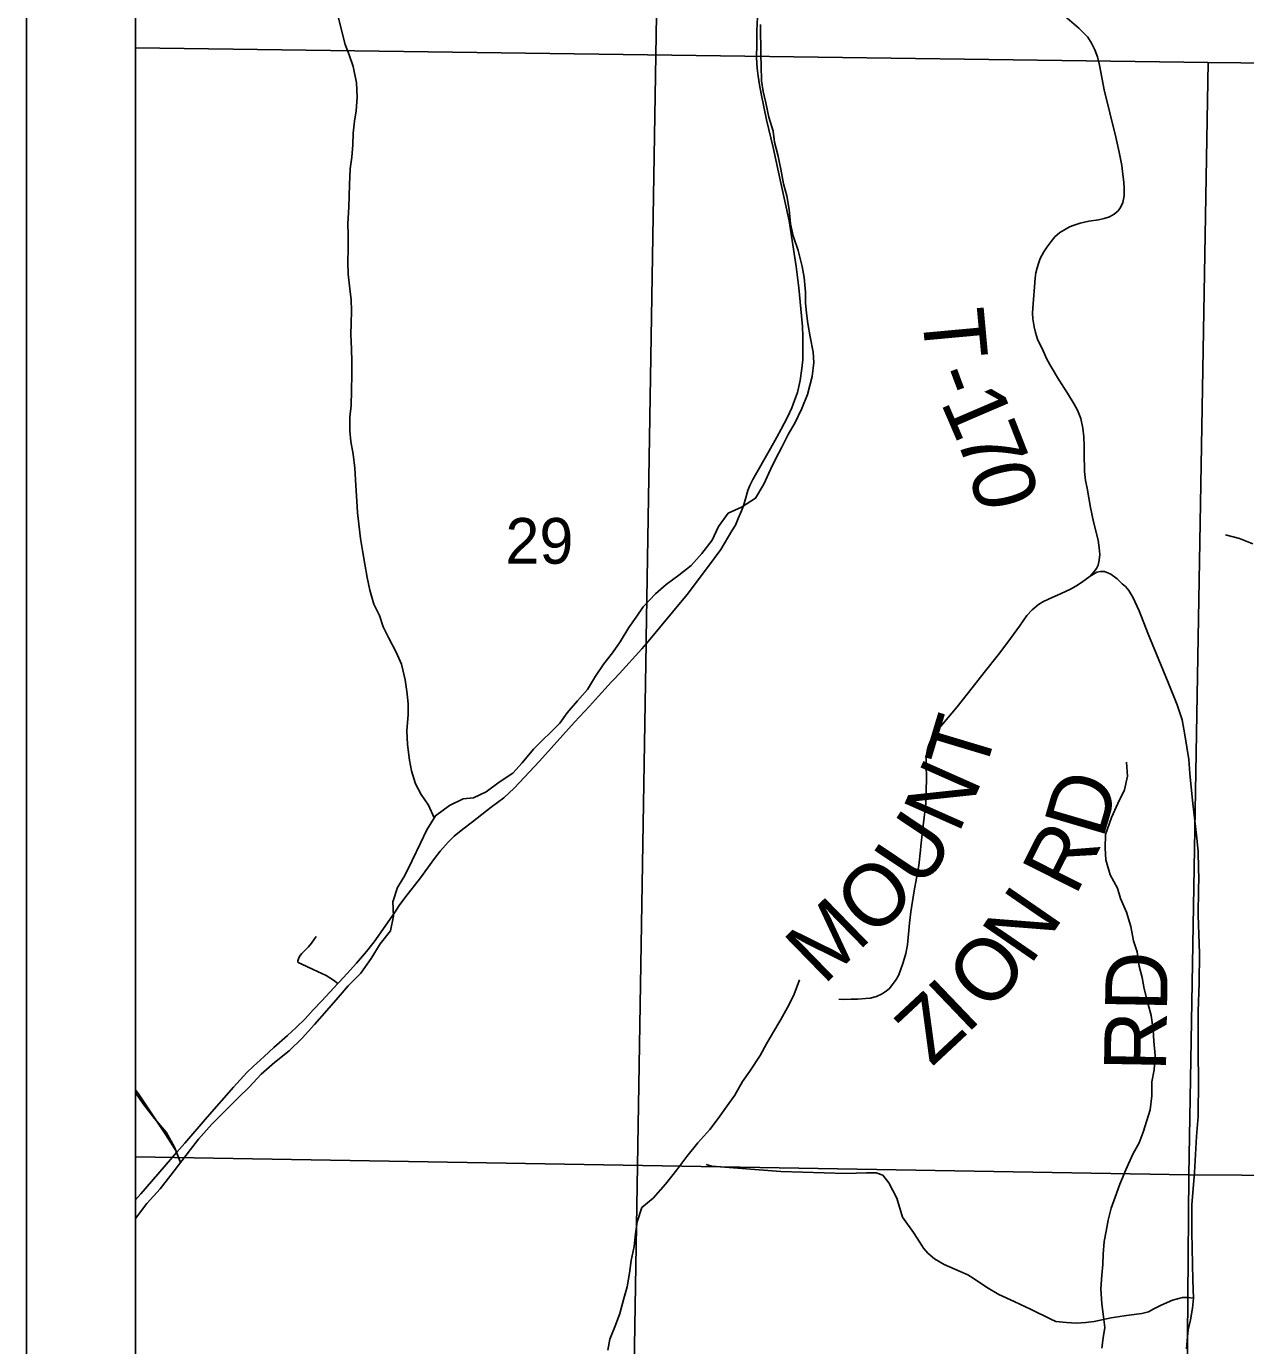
# Model space of a CAD drawing. Extents: x 0 to 34, y -8.9 to 22.
# Drawn here: x 23.617 to 24.734, y 10.111 to 11.32 of the extents above; entities that cross this region are included whole.
import ezdxf

# ---------------------------------------------------------------- set-up
doc = ezdxf.new("R2010")
doc.units = 0
for name, color, linetype in [('GM_X_Corporation', 7, 'Continuous'), ('GM_X_County_Road', 7, 'Continuous'), ('GM_X_Minor_River', 7, 'Continuous'), ('GM_X_Section_Text', 7, 'Continuous'), ('GM_X_Township_Road', 7, 'Continuous'), ('GM_X_Township_Road_Text', 7, 'Continuous'), ('SH_Data', 7, 'Continuous')]:
    doc.layers.add(name, color=color, linetype=linetype)

msp = doc.modelspace()

# ---------------------------------------------------------------- linework, layer by layer
at = {"layer": 'GM_X_Corporation'}
for points in [[(27.1396, 11.9157), (26.2139, 11.9314), (25.7578, 11.9372), (25.7218, 11.9377), (25.1035, 11.9505), (25.0773, 11.948), (24.3163, 11.9608), (24.2054, 11.9625), (24.1849, 11.9621), (23.7167, 11.9654), (23.7167, 7.104)], [(27.1396, 11.9157), (26.2139, 11.9314), (25.7578, 11.9372), (25.7218, 11.9377), (25.1035, 11.9505), (25.0773, 11.948), (24.3163, 11.9608), (24.2054, 11.9625), (24.2028, 11.8378), (24.2025, 11.824), (24.2007, 11.7362), (24.1845, 10.7587), (24.1844, 10.755), (24.1596, 9.2636)]]:
    msp.add_lwpolyline(points, dxfattribs=at)
for points in [[(23.7167, 11.9654), (23.7167, 9.2682), (24.0743, 9.2644), (24.1596, 9.2636), (24.1844, 10.755), (24.1845, 10.7587), (24.2007, 11.7362), (24.2025, 11.824), (24.2028, 11.8378), (24.2054, 11.9625), (24.1849, 11.9621)], [(23.7167, 11.3004), (23.7167, 10.2843), (24.6816, 10.2678), (24.6992, 11.287)], [(24.6992, 11.287), (25.7123, 11.2765), (25.698, 10.2614), (24.6816, 10.2678)], [(23.7167, 10.2843), (23.7167, 9.2652), (24.6733, 9.2562), (24.6816, 10.2678)], [(24.6816, 10.2678), (25.698, 10.2614), (25.683, 9.2467), (24.6733, 9.2562)]]:
    msp.add_lwpolyline(points, close=True, dxfattribs=at)
at = {"layer": 'GM_X_County_Road'}
for points in [[(24.1599, 10.7272), (24.1804, 10.7498), (24.1846, 10.7545), (24.2086, 10.7832), (24.2221, 10.7996), (24.2407, 10.8243), (24.2527, 10.8408), (24.263, 10.8578), (24.2662, 10.8631), (24.2688, 10.8692), (24.2718, 10.876), (24.2736, 10.8808), (24.2755, 10.8871), (24.2775, 10.8947), (24.2795, 10.8994), (24.2822, 10.9049), (24.2983, 10.9333), (24.3042, 10.9437), (24.3082, 10.9511), (24.3135, 10.9614), (24.3178, 10.9704), (24.3204, 10.9771), (24.323, 10.9847), (24.3254, 10.9954), (24.3271, 11.0065), (24.3279, 11.0145), (24.3279, 11.0221), (24.3279, 11.036), (24.3276, 11.0449), (24.3262, 11.0611), (24.3242, 11.0805), (24.3219, 11.1), (24.3195, 11.1159), (24.3153, 11.1417), (24.3082, 11.175), (24.3008, 11.2089), (24.2948, 11.2344), (24.2898, 11.2583), (24.2882, 11.2665), (24.287, 11.2743), (24.2862, 11.2817), (24.2854, 11.2911), (24.2857, 11.3038), (24.2859, 11.3163), (24.2863, 11.3286)], [(23.7167, 10.2448), (23.7216, 10.2503), (23.7545, 10.2886), (23.7617, 10.2966), (23.7824, 10.3205), (23.8065, 10.3482), (23.8187, 10.3614), (23.8243, 10.367), (23.8345, 10.3762), (23.8435, 10.3844), (23.856, 10.3955), (23.8637, 10.4026), (23.8719, 10.4108), (23.8794, 10.4188), (23.8873, 10.4272), (23.9019, 10.4429), (23.9033, 10.4444), (23.9104, 10.4522), (23.9191, 10.4617), (23.9283, 10.4723), (23.9354, 10.4811), (23.9538, 10.5078), (23.9583, 10.5144), (23.9634, 10.5215), (23.9778, 10.5399), (23.9905, 10.5576), (23.9957, 10.5644), (24.003, 10.5725), (24.0085, 10.5779), (24.0166, 10.5845), (24.0253, 10.5913), (24.0424, 10.6045), (24.0539, 10.6133), (24.0634, 10.622), (24.0868, 10.6468), (24.1189, 10.6825), (24.1324, 10.697), (24.1407, 10.7062), (24.1528, 10.7193), (24.1551, 10.7219), (24.1599, 10.7272)]]:
    msp.add_lwpolyline(points, dxfattribs=at)
at = {"layer": 'GM_X_Minor_River'}
for points in [[(23.9902, 10.5949), (23.9849, 10.6063), (23.9784, 10.6161), (23.973, 10.626), (23.9696, 10.6378), (23.9677, 10.6476), (23.9657, 10.6621), (23.9653, 10.6746), (23.9664, 10.6894), (23.9664, 10.6989), (23.9656, 10.7084), (23.9637, 10.7213), (23.9602, 10.7357), (23.9553, 10.7467), (23.9484, 10.76), (23.9435, 10.7699), (23.94, 10.7801), (23.9351, 10.7907), (23.9312, 10.8033), (23.9289, 10.815), (23.9266, 10.8272), (23.9247, 10.8397), (23.9228, 10.8507), (23.9212, 10.864), (23.9201, 10.8746), (23.9193, 10.8849), (23.9185, 10.8993), (23.9177, 10.9153), (23.9161, 10.9282), (23.9138, 10.9396), (23.913, 10.9494), (23.913, 10.962), (23.9141, 10.9726), (23.9145, 10.9863), (23.9148, 11.0011), (23.9148, 11.0129), (23.9144, 11.0243), (23.9139, 11.038), (23.9143, 11.0475), (23.9146, 11.0596), (23.9142, 11.0695), (23.9131, 11.0794), (23.9115, 11.093), (23.9111, 11.1037), (23.9115, 11.1166), (23.9114, 11.1291), (23.911, 11.139), (23.9121, 11.1546), (23.9125, 11.1645), (23.9128, 11.1751), (23.9132, 11.1895), (23.9147, 11.2002), (23.9158, 11.2116), (23.9161, 11.2222), (23.9172, 11.2332), (23.9187, 11.2427), (23.9198, 11.2553), (23.9191, 11.2682), (23.916, 11.2834), (23.9125, 11.294), (23.9087, 11.3035), (23.9053, 11.3164), (23.9026, 11.3278)], [(24.2143, 10.8171), (24.2256, 10.8259), (24.2355, 10.8369), (24.2449, 10.8491), (24.2506, 10.8617), (24.2597, 10.8739), (24.2718, 10.8796), (24.2847, 10.8876), (24.2922, 10.9006), (24.2983, 10.9139), (24.3028, 10.9234), (24.3088, 10.9344), (24.3149, 10.9466), (24.3206, 10.9565), (24.327, 10.9698), (24.3322, 10.9828), (24.3364, 10.9991), (24.3379, 11.012), (24.3375, 11.0215), (24.3348, 11.0356), (24.3325, 11.0477), (24.3313, 11.0572), (24.3305, 11.0667), (24.3305, 11.0766), (24.3293, 11.0899), (24.3274, 11.1001), (24.3236, 11.1146), (24.319, 11.1282), (24.3167, 11.1392), (24.3155, 11.1521), (24.3132, 11.1647), (24.3101, 11.1757), (24.3078, 11.1893), (24.3051, 11.2022), (24.3021, 11.214), (24.3009, 11.2239), (24.2967, 11.2368), (24.294, 11.2501), (24.2917, 11.2603), (24.2902, 11.2702), (24.2898, 11.2842), (24.2894, 11.2937), (24.2893, 11.3218)], [(24.7401, 10.8459), (24.728, 10.8508), (24.7151, 10.8541)], [(23.7167, 10.2278), (23.727, 10.2415), (23.7391, 10.2548), (23.7489, 10.2674), (23.7591, 10.2807), (23.7671, 10.291), (23.7743, 10.3005), (23.7864, 10.3143), (23.7985, 10.3261), (23.811, 10.3386), (23.8208, 10.3482), (23.8318, 10.36), (23.8439, 10.3707), (23.8575, 10.3813), (23.8693, 10.3928), (23.8806, 10.4054), (23.892, 10.4183), (23.9022, 10.4301), (23.9113, 10.4408), (23.923, 10.4526), (23.9325, 10.4659), (23.9408, 10.4793), (23.9502, 10.4914), (23.9529, 10.5047), (23.9524, 10.518), (23.9566, 10.531), (23.9634, 10.542), (23.9702, 10.5557), (23.9777, 10.5717), (23.9834, 10.5839), (23.9913, 10.5968), (24.0042, 10.606), (24.0167, 10.6121), (24.0262, 10.6133), (24.0379, 10.6186), (24.0497, 10.6274), (24.0622, 10.6358), (24.0709, 10.6453), (24.0811, 10.6579), (24.1053, 10.6815), (24.1121, 10.691), (24.1216, 10.7021), (24.1307, 10.7124), (24.1379, 10.7246), (24.1458, 10.736), (24.1537, 10.7459), (24.1605, 10.7562), (24.1685, 10.7691), (24.1753, 10.7786), (24.1817, 10.7881), (24.1931, 10.8), (24.2029, 10.8087), (24.2143, 10.8171)], [(24.6029, 10.1856), (24.6032, 10.1951), (24.604, 10.2065), (24.6059, 10.216), (24.6077, 10.2262), (24.6104, 10.2373), (24.6141, 10.2472), (24.6183, 10.2593), (24.6239, 10.2723), (24.6303, 10.2867), (24.636, 10.297), (24.6398, 10.3069), (24.6432, 10.3175), (24.6462, 10.3274), (24.6477, 10.34), (24.6476, 10.3529), (24.6499, 10.3639), (24.6506, 10.3772), (24.6494, 10.3901), (24.649, 10.4007), (24.6471, 10.4136), (24.6437, 10.4262), (24.6406, 10.4383), (24.6387, 10.4486), (24.636, 10.4588), (24.6341, 10.4721), (24.631, 10.482), (24.6283, 10.4952), (24.6245, 10.5085), (24.6191, 10.521), (24.6161, 10.5305), (24.6096, 10.5427), (24.6054, 10.5563), (24.605, 10.567), (24.6053, 10.5795), (24.6106, 10.5951), (24.6166, 10.608), (24.6227, 10.6206), (24.6253, 10.6331), (24.6245, 10.6457)], [(24.1493, 10.107), (24.1511, 10.1172), (24.1564, 10.1301), (24.1602, 10.1408), (24.1639, 10.1545), (24.1669, 10.1651), (24.1692, 10.1777), (24.1707, 10.1891), (24.1733, 10.202), (24.1748, 10.2138), (24.1763, 10.2248), (24.1804, 10.2377), (24.1907, 10.2465), (24.202, 10.2591), (24.2126, 10.2724), (24.2217, 10.2846), (24.2319, 10.2971), (24.2429, 10.3093), (24.2504, 10.3192), (24.2587, 10.331), (24.2656, 10.3406), (24.2727, 10.3531), (24.2795, 10.3626), (24.289, 10.3771), (24.2947, 10.3878), (24.3003, 10.3973), (24.3079, 10.4102), (24.3154, 10.4239), (24.32, 10.4334), (24.3249, 10.4464)], [(23.7577, 10.2789), (23.7523, 10.2932), (23.7447, 10.3069), (23.734, 10.3194), (23.7237, 10.3327), (23.7169, 10.3425), (23.7167, 10.3428)], [(24.6019, 10.1089), (24.6031, 10.1184), (24.6046, 10.1279), (24.603, 10.14), (24.6018, 10.1495), (24.601, 10.1632), (24.6018, 10.1757), (24.6029, 10.1856)]]:
    msp.add_lwpolyline(points, dxfattribs=at)
at = {"layer": 'GM_X_Township_Road'}
for points in [[(24.361, 10.4288), (24.3648, 10.4285), (24.3721, 10.4286), (24.3784, 10.4287), (24.3854, 10.4292), (24.3897, 10.4297), (24.3953, 10.4312), (24.4007, 10.4337), (24.4045, 10.4362), (24.4069, 10.4382), (24.4093, 10.4409), (24.4135, 10.4466), (24.4155, 10.4503), (24.4172, 10.4544), (24.4198, 10.4622), (24.4222, 10.4705), (24.4237, 10.4784), (24.4257, 10.4983), (24.427, 10.5086), (24.4301, 10.5278), (24.4341, 10.5512), (24.4358, 10.5651), (24.4362, 10.569), (24.4374, 10.5799), (24.4392, 10.5954), (24.4405, 10.6076), (24.441, 10.6172), (24.4411, 10.6332), (24.4408, 10.6412), (24.4409, 10.6488), (24.4411, 10.6526), (24.4421, 10.6577), (24.4433, 10.6616), (24.4451, 10.6659), (24.4472, 10.6692), (24.4499, 10.6732), (24.4563, 10.6811), (24.4692, 10.6966), (24.4832, 10.714), (24.4942, 10.7279), (24.5072, 10.7446), (24.5158, 10.7558), (24.5264, 10.7705), (24.5333, 10.7802), (24.5379, 10.7854), (24.5437, 10.7902), (24.5479, 10.7928), (24.5529, 10.7952), (24.5646, 10.8004), (24.5687, 10.8023), (24.5731, 10.8044), (24.578, 10.8071), (24.5833, 10.8106), (24.5912, 10.8162), (24.595, 10.8206), (24.597, 10.8234), (24.5985, 10.8264), (24.5993, 10.8309), (24.5999, 10.8361), (24.5995, 10.8423), (24.5984, 10.8493), (24.5943, 10.8661), (24.5916, 10.8793), (24.5883, 10.8968), (24.5869, 10.9038), (24.5861, 10.9123), (24.5858, 10.9291), (24.5858, 10.9354), (24.5853, 10.9438), (24.5846, 10.9519), (24.5826, 10.9607), (24.5797, 10.9683), (24.5766, 10.974), (24.5703, 10.984), (24.5621, 10.9968), (24.5556, 11.008), (24.5516, 11.015), (24.548, 11.0226), (24.543, 11.0334), (24.5411, 11.0396), (24.5398, 11.0446), (24.5386, 11.0519), (24.5385, 11.0571), (24.5388, 11.0617), (24.5408, 11.0893), (24.5414, 11.0943), (24.5425, 11.0987), (24.5438, 11.1026), (24.5455, 11.1074), (24.5486, 11.1133), (24.5517, 11.1181), (24.5555, 11.123), (24.5589, 11.1271), (24.5634, 11.131), (24.5677, 11.1337), (24.5722, 11.1363), (24.5766, 11.138), (24.582, 11.1397), (24.5901, 11.1415), (24.5988, 11.1428), (24.604, 11.144), (24.609, 11.1456), (24.6132, 11.1479), (24.6167, 11.1511), (24.619, 11.1542), (24.6212, 11.1587), (24.6223, 11.1647), (24.6223, 11.1714), (24.622, 11.1772), (24.621, 11.1843), (24.6202, 11.1925), (24.6177, 11.2047), (24.6147, 11.2184), (24.6092, 11.2407), (24.6041, 11.262), (24.5997, 11.2846), (24.5979, 11.2921), (24.5956, 11.2985), (24.5923, 11.3046), (24.589, 11.31), (24.5855, 11.3138), (24.5808, 11.3183), (24.5658, 11.3311)], [(24.6793, 10.1082), (24.6799, 10.116), (24.6811, 10.1258), (24.6831, 10.1349), (24.6848, 10.1455), (24.6857, 10.1548), (24.6851, 10.1712), (24.6843, 10.2151), (24.6842, 10.2403), (24.6868, 10.27), (24.6885, 10.3027), (24.6902, 10.3211), (24.6904, 10.3552), (24.6901, 10.3786), (24.6901, 10.4173), (24.6911, 10.4436), (24.6913, 10.4704), (24.6902, 10.5055), (24.6904, 10.5294), (24.6907, 10.5391), (24.6905, 10.5486), (24.69, 10.5637), (24.6889, 10.5763), (24.685, 10.6106), (24.6825, 10.6354), (24.6816, 10.6484), (24.678, 10.671), (24.6754, 10.6845), (24.6708, 10.6985), (24.6626, 10.7188), (24.6561, 10.7345), (24.6439, 10.7641), (24.636, 10.7845), (24.6304, 10.797), (24.6265, 10.8032), (24.6235, 10.8067), (24.6206, 10.8092), (24.6158, 10.8137), (24.61, 10.8182), (24.6043, 10.8205), (24.6007, 10.8205), (24.5972, 10.8199), (24.5912, 10.8162)], [(23.8821, 10.4861), (23.8779, 10.4799), (23.8751, 10.4766), (23.8727, 10.4743), (23.8706, 10.4721), (23.8689, 10.4706), (23.8676, 10.4687), (23.8664, 10.4665), (23.8657, 10.4648), (23.8654, 10.4638), (23.8654, 10.4627), (23.8662, 10.462), (23.8685, 10.461), (23.8793, 10.456), (23.8912, 10.4503), (23.8979, 10.4462), (23.9019, 10.4429)], [(23.7545, 10.2886), (23.7444, 10.3044), (23.7193, 10.3419), (23.7167, 10.3457)], [(24.2393, 10.2772), (24.2446, 10.2756), (24.3079, 10.2708), (24.3674, 10.2688), (24.3864, 10.2697), (24.3951, 10.2697), (24.4011, 10.2673), (24.4068, 10.2604), (24.4142, 10.2463), (24.4194, 10.2288), (24.4292, 10.215), (24.4354, 10.2055), (24.4385, 10.2005), (24.4426, 10.1961), (24.4486, 10.1909), (24.4575, 10.1856), (24.4722, 10.1792), (24.479, 10.176), (24.4848, 10.1724), (24.4962, 10.1648), (24.5074, 10.1581), (24.5217, 10.1518), (24.5372, 10.1444), (24.5551, 10.1356), (24.5598, 10.1334), (24.5695, 10.1323), (24.5786, 10.1318), (24.5872, 10.1323), (24.5947, 10.1334), (24.6103, 10.1366), (24.6224, 10.1386), (24.6335, 10.1401), (24.6386, 10.1408), (24.6445, 10.1422), (24.6495, 10.1451), (24.6556, 10.148), (24.6617, 10.1509), (24.6665, 10.1528), (24.6712, 10.1542), (24.6759, 10.1552), (24.6806, 10.1553), (24.6857, 10.1548)]]:
    msp.add_lwpolyline(points, dxfattribs=at)
at = {"layer": 'SH_Data'}
for points in [[(23.6167, 14.004), (30.6167, 14.004), (30.6167, 7.004), (23.6167, 7.004)], [(23.7167, 13.904), (30.5167, 13.904), (30.5167, 7.104), (23.7167, 7.104)]]:
    msp.add_lwpolyline(points, close=True, dxfattribs=at)

# ---------------------------------------------------------------- texts
at = {"layer": 'GM_X_Section_Text'}
msp.add_text('29', height=0.04186, rotation=0, dxfattribs=at).set_placement((24.0555, 10.8277))
at = {"layer": 'GM_X_Township_Road_Text'}
for s, height, rotation, p in [('T', 0.0568, 275.2573, (24.4369, 11.0589)), ('-', 0.0568, 290.4386, (24.4445, 11.0006)), ('1', 0.0568, 293.2345, (24.4538, 10.9759)), ('7', 0.0568, 291.4149, (24.4674, 10.9442)), ('0', 0.0568, 283.9706, (24.4796, 10.9135)), ('T', 0.0568, 73.2772, (24.4936, 10.6324)), ('N', 0.0568, 66.0455, (24.4705, 10.5793)), ('D', 0.0568, 73.6408, (24.6027, 10.5744)), ('U', 0.0568, 56.1315, (24.4375, 10.5284)), ('R', 0.0568, 63.2907, (24.5777, 10.5223)), ('O', 0.0568, 42.3278, (24.3908, 10.4835)), ('N', 0.0568, 55.4169, (24.5362, 10.4587)), ('M', 0.0568, 44.2585, (24.347, 10.4408)), ('O', 0.0568, 48.0129, (24.4978, 10.4152)), ('RD', 0.05682, 89.0127, (24.6606, 10.3622)), ('I', 0.0568, 43.7437, (24.4777, 10.3958)), ('Z', 0.0568, 43.0359, (24.4461, 10.3662))]:
    msp.add_text(s, height=height, rotation=rotation, dxfattribs=at).set_placement(p)

doc.saveas('drawing.dxf')
